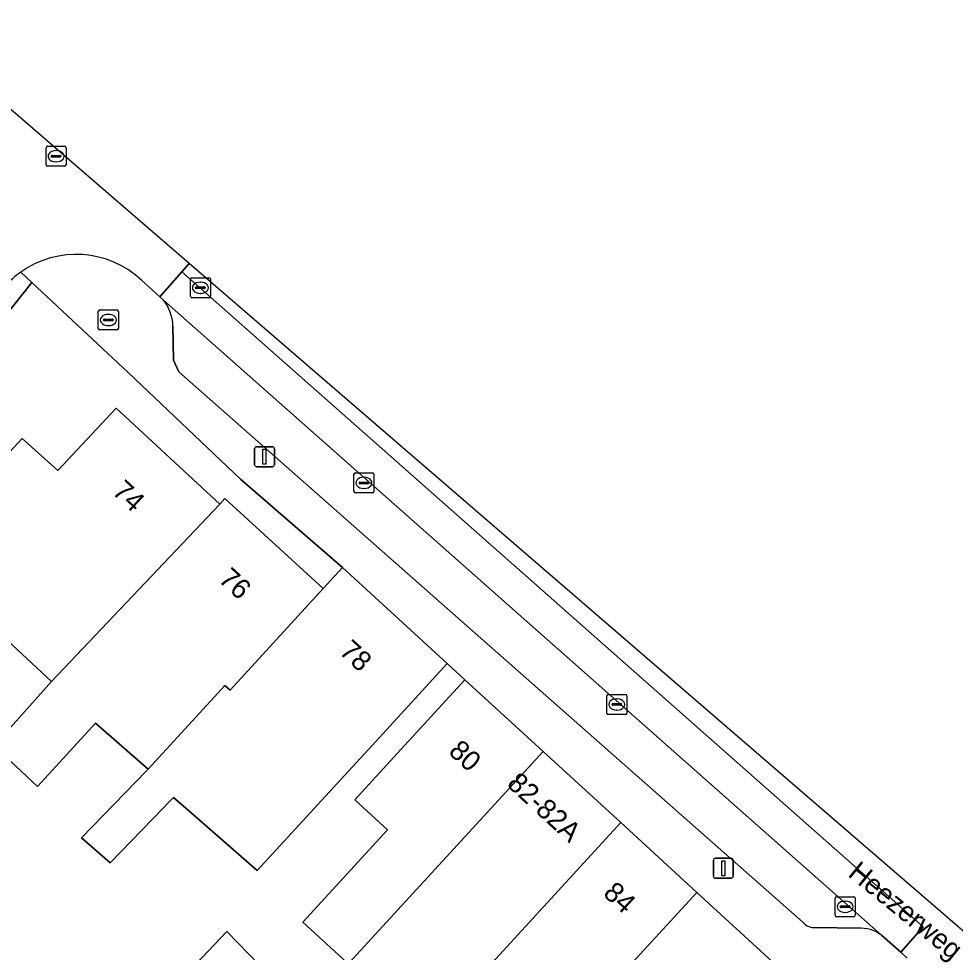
# Model space of a CAD drawing. Extents: x 161881 to 162523, y 381678 to 382381.
# Drawn here: x 162115.53 to 162162.08, y 382136.5 to 382183.09 of the extents above; entities that cross this region are included whole.
import ezdxf

# ---------------------------------------------------------------- set-up
doc = ezdxf.new("R2010")
doc.units = 0
for name, color, linetype in [('IMGEO_Brandkraan', 7, 'Continuous'), ('IMGEO_Erf', 7, 'Continuous'), ('IMGEO_Kolk', 7, 'Continuous'), ('IMGEO_Lichtmast', 7, 'Continuous'), ('IMGEO_Openbare_ruimte_label', 7, 'Continuous'), ('IMGEO_Pand', 7, 'Continuous'), ('IMGEO_Pand_nummerreeks', 7, 'Continuous'), ('IMGEO_Parkeervlak_open', 7, 'Continuous'), ('IMGEO_Rijbaan_lokaal_gesloten', 7, 'Continuous'), ('IMGEO_Rijbaan_lokaal_open', 7, 'Continuous'), ('IMGEO_Rioolput', 7, 'Continuous'), ('IMGEO_Voetpad_open', 7, 'Continuous')]:
    doc.layers.add(name, color=color, linetype=linetype)

msp = doc.modelspace()

# ---------------------------------------------------------------- linework, layer by layer
at = {"layer": 'IMGEO_Brandkraan'}
for p, q in [((162119.584, 382168.556), (162120.436, 382168.556)), ((162119.509, 382167.63), (162119.509, 382168.482)), ((162119.768, 382168.05), (162119.768, 382168.062)), ((162119.811, 382168.099), (162120.209, 382168.099)), ((162119.997, 382168.336), (162120.022, 382168.336)), ((162120.252, 382168.062), (162120.252, 382168.05)), ((162120.51, 382168.482), (162120.51, 382167.63)), ((162120.206, 382168.013), (162119.808, 382168.013)), ((162120.02, 382167.776), (162119.995, 382167.776)), ((162120.436, 382167.556), (162119.584, 382167.556))]:
    msp.add_line(p, q, dxfattribs=at)
for points in [[(162119.584, 382168.556), (162120.436, 382168.556)], [(162119.509, 382167.63), (162119.509, 382168.482)], [(162120.51, 382168.482), (162120.51, 382167.63)], [(162120.436, 382167.556), (162119.584, 382167.556)]]:
    msp.add_lwpolyline(points, dxfattribs=at)
for centre, radius, start, end in [((162119.586, 382168.48), 0.0765, 91.552, 178.448), ((162119.586, 382168.48), 0.0765, 91.552, 178.448), ((162120.434, 382168.48), 0.0765, 1.552, 88.448), ((162120.434, 382168.48), 0.0765, 1.552, 88.448), ((162119.808, 382168.059), 0.0403, 85.8775, 175.7526), ((162119.805, 382168.049), 0.0366, 178.938, 274.7102), ((162120.209, 382168.056), 0.043, 264.8664, 352.4533), ((162120.213, 382168.061), 0.0386, 1.7309, 96.639), ((162119.586, 382167.632), 0.0765, 181.552, 268.448), ((162119.586, 382167.632), 0.0765, 181.552, 268.448), ((162120.434, 382167.632), 0.0765, 271.552, 358.448), ((162120.434, 382167.632), 0.0765, 271.552, 358.448)]:
    msp.add_arc(centre, radius, start, end, dxfattribs=at)
for centre, major_axis, ratio, start_param, end_param in [((162119.996, 382168.056), (-0.387, 0.002), 0.722429, 4.712389, 7.853982), ((162120.021, 382168.056), (-0.39, 0.002), 0.717154, 1.570796, 4.712389)]:
    msp.add_ellipse(centre, major_axis=major_axis, ratio=ratio, start_param=start_param, end_param=end_param, dxfattribs=at)
at = {"layer": 'IMGEO_Erf'}
for points in [[(162112.301, 382158.48), (162115.707, 382162.139), (162117.492, 382160.54), (162120.395, 382163.662), (162125.568, 382158.867), (162125.829, 382159.152), (162130.734, 382154.653), (162131.693, 382155.698), (162126.612, 382160.118), (162121.003, 382165.434), (162116.187, 382169.927), (162097.305, 382146.167)], [(162131.894, 382136.009), (162129.716, 382138.006), (162133.943, 382142.615), (162132.309, 382144.112), (162134.424, 382146.419), (162137.803, 382150.104), (162136.914, 382150.91), (162133.535, 382147.226), (162131.051, 382144.517), (162127.442, 382140.582), (162124.386, 382143.249), (162124.15, 382143.466), (162123.259, 382144.232), (162123.015, 382143.98), (162122.764, 382143.72), (162120.096, 382140.962), (162118.667, 382142.21), (162121.906, 382145.559), (162121.989, 382145.649), (162119.367, 382147.936), (162116.48, 382144.785), (162114.301, 382146.812), (162117.176, 382150.009), (162110.339, 382156.373)], [(162120.058, 382131.359), (162125.918, 382137.539), (162129.757, 382133.588)]]:
    msp.add_lwpolyline(points, dxfattribs=at)
at = {"layer": 'IMGEO_Kolk'}
for p, q in [((162132.263, 382159.501), (162132.263, 382160.353)), ((162132.338, 382160.427), (162133.19, 382160.427)), ((162132.751, 382160.207), (162132.776, 382160.207)), ((162133.264, 382160.353), (162133.264, 382159.501)), ((162132.522, 382159.921), (162132.522, 382159.933)), ((162132.96, 382159.884), (162132.562, 382159.884)), ((162132.565, 382159.97), (162132.963, 382159.97)), ((162132.774, 382159.647), (162132.749, 382159.647)), ((162133.006, 382159.933), (162133.006, 382159.921)), ((162133.19, 382159.427), (162132.338, 382159.427)), ((162144.88, 382148.444), (162144.88, 382149.296)), ((162144.955, 382149.37), (162145.807, 382149.37)), ((162145.368, 382149.15), (162145.393, 382149.15)), ((162145.881, 382149.296), (162145.881, 382148.444)), ((162145.139, 382148.864), (162145.139, 382148.876)), ((162145.577, 382148.827), (162145.179, 382148.827)), ((162145.182, 382148.913), (162145.58, 382148.913)), ((162145.391, 382148.59), (162145.366, 382148.59)), ((162145.623, 382148.876), (162145.623, 382148.864)), ((162145.807, 382148.37), (162144.955, 382148.37)), ((162156.274, 382138.351), (162156.274, 382139.203)), ((162156.349, 382139.277), (162157.201, 382139.277)), ((162157.275, 382139.203), (162157.275, 382138.351)), ((162156.533, 382138.771), (162156.533, 382138.783)), ((162156.971, 382138.734), (162156.573, 382138.734)), ((162156.576, 382138.82), (162156.974, 382138.82)), ((162156.762, 382139.057), (162156.787, 382139.057)), ((162157.017, 382138.783), (162157.017, 382138.771)), ((162157.201, 382138.277), (162156.349, 382138.277)), ((162156.785, 382138.497), (162156.76, 382138.497))]:
    msp.add_line(p, q, dxfattribs=at)
for points in [[(162132.263, 382159.501), (162132.263, 382160.353)], [(162132.338, 382160.427), (162133.19, 382160.427)], [(162133.264, 382160.353), (162133.264, 382159.501)], [(162133.19, 382159.427), (162132.338, 382159.427)], [(162144.88, 382148.444), (162144.88, 382149.296)], [(162144.955, 382149.37), (162145.807, 382149.37)], [(162145.881, 382149.296), (162145.881, 382148.444)], [(162145.807, 382148.37), (162144.955, 382148.37)], [(162156.274, 382138.351), (162156.274, 382139.203)], [(162156.349, 382139.277), (162157.201, 382139.277)], [(162157.275, 382139.203), (162157.275, 382138.351)], [(162157.201, 382138.277), (162156.349, 382138.277)]]:
    msp.add_lwpolyline(points, dxfattribs=at)
for centre, radius, start, end in [((162132.34, 382160.351), 0.0765, 91.552, 178.448), ((162132.34, 382160.351), 0.0765, 91.552, 178.448), ((162133.188, 382160.351), 0.0765, 1.552, 88.448), ((162133.188, 382160.351), 0.0765, 1.552, 88.448), ((162132.562, 382159.93), 0.0403, 85.8775, 175.7526), ((162132.559, 382159.92), 0.0366, 178.938, 274.7102), ((162132.963, 382159.927), 0.043, 264.8664, 352.4533), ((162132.967, 382159.932), 0.0386, 1.7309, 96.639), ((162132.34, 382159.503), 0.0765, 181.552, 268.448), ((162132.34, 382159.503), 0.0765, 181.552, 268.448), ((162133.188, 382159.503), 0.0765, 271.552, 358.448), ((162133.188, 382159.503), 0.0765, 271.552, 358.448), ((162144.957, 382149.294), 0.0765, 91.552, 178.448), ((162144.957, 382149.294), 0.0765, 91.552, 178.448), ((162145.805, 382149.294), 0.0765, 1.552, 88.448), ((162145.805, 382149.294), 0.0765, 1.552, 88.448), ((162145.179, 382148.873), 0.0403, 85.8775, 175.7526), ((162145.176, 382148.863), 0.0366, 178.938, 274.7102), ((162145.58, 382148.87), 0.043, 264.8664, 352.4533), ((162145.584, 382148.875), 0.0386, 1.7309, 96.639), ((162144.957, 382148.446), 0.0765, 181.552, 268.448), ((162144.957, 382148.446), 0.0765, 181.552, 268.448), ((162145.805, 382148.446), 0.0765, 271.552, 358.448), ((162145.805, 382148.446), 0.0765, 271.552, 358.448), ((162156.351, 382139.201), 0.0765, 91.552, 178.448), ((162156.351, 382139.201), 0.0765, 91.552, 178.448), ((162157.199, 382139.201), 0.0765, 1.552, 88.448), ((162157.199, 382139.201), 0.0765, 1.552, 88.448), ((162156.573, 382138.78), 0.0403, 85.8775, 175.7526), ((162156.57, 382138.77), 0.0366, 178.938, 274.7102), ((162156.974, 382138.777), 0.043, 264.8664, 352.4533), ((162156.978, 382138.782), 0.0386, 1.7309, 96.639), ((162156.351, 382138.353), 0.0765, 181.552, 268.448), ((162156.351, 382138.353), 0.0765, 181.552, 268.448), ((162157.199, 382138.353), 0.0765, 271.552, 358.448), ((162157.199, 382138.353), 0.0765, 271.552, 358.448)]:
    msp.add_arc(centre, radius, start, end, dxfattribs=at)
for centre, major_axis, ratio, start_param, end_param in [((162132.75, 382159.927), (-0.387, 0.002), 0.722429, 4.712389, 7.853982), ((162132.775, 382159.927), (-0.39, 0.002), 0.717154, 1.570796, 4.712389), ((162145.367, 382148.87), (-0.387, 0.002), 0.722429, 4.712389, 7.853982), ((162145.392, 382148.87), (-0.39, 0.002), 0.717154, 1.570796, 4.712389), ((162156.761, 382138.777), (-0.387, 0.002), 0.722429, 4.712389, 7.853982), ((162156.786, 382138.777), (-0.39, 0.002), 0.717154, 1.570796, 4.712389)]:
    msp.add_ellipse(centre, major_axis=major_axis, ratio=ratio, start_param=start_param, end_param=end_param, dxfattribs=at)
at = {"layer": 'IMGEO_Lichtmast'}
for p, q in [((162127.306, 382160.831), (162127.306, 382161.631)), ((162127.306, 382161.631), (162127.306, 382160.831)), ((162127.406, 382161.731), (162128.196, 382161.731)), ((162128.196, 382161.731), (162127.406, 382161.731)), ((162128.296, 382161.631), (162128.296, 382160.831)), ((162128.296, 382160.831), (162128.296, 382161.631)), ((162128.196, 382160.731), (162127.406, 382160.731)), ((162127.406, 382160.731), (162128.196, 382160.731)), ((162150.201, 382140.3), (162150.201, 382141.1)), ((162150.201, 382141.1), (162150.201, 382140.3)), ((162150.301, 382141.2), (162151.091, 382141.2)), ((162151.091, 382141.2), (162150.301, 382141.2)), ((162151.191, 382141.1), (162151.191, 382140.3)), ((162151.191, 382140.3), (162151.191, 382141.1)), ((162151.091, 382140.2), (162150.301, 382140.2)), ((162150.301, 382140.2), (162151.091, 382140.2))]:
    msp.add_line(p, q, dxfattribs=at)
for points in [[(162127.726, 382161.606), (162127.876, 382161.606), (162127.876, 382160.856), (162127.726, 382160.856), (162127.726, 382161.606)], [(162150.621, 382141.075), (162150.771, 382141.075), (162150.771, 382140.325), (162150.621, 382140.325), (162150.621, 382141.075)]]:
    msp.add_lwpolyline(points, dxfattribs=at)
for centre, start, end in [((162127.406, 382161.631), 90, 180), ((162127.406, 382161.631), 90, 180), ((162128.196, 382161.631), 0, 90), ((162128.196, 382161.631), 360, 90), ((162127.406, 382160.831), 180, 270), ((162127.406, 382160.831), 180, 270), ((162128.196, 382160.831), 270, 0), ((162128.196, 382160.831), 270, 0), ((162150.301, 382141.1), 90, 180), ((162150.301, 382141.1), 90, 180), ((162151.091, 382141.1), 0, 90), ((162151.091, 382141.1), 360, 90), ((162150.301, 382140.3), 180, 270), ((162150.301, 382140.3), 180, 270), ((162151.091, 382140.3), 270, 0), ((162151.091, 382140.3), 270, 0)]:
    msp.add_arc(centre, 0.1, start, end, dxfattribs=at)
at = {"layer": 'IMGEO_Pand'}
for points in [[(162125.568, 382158.867), (162120.395, 382163.662), (162117.492, 382160.54), (162115.707, 382162.139), (162112.301, 382158.48), (162110.339, 382156.373), (162117.176, 382150.009)], [(162130.734, 382154.653), (162125.829, 382159.152), (162125.568, 382158.867), (162117.176, 382150.009), (162114.301, 382146.812), (162116.48, 382144.785), (162119.367, 382147.936), (162121.989, 382145.649), (162125.818, 382149.824), (162126.084, 382149.58)], [(162133.535, 382147.226), (162136.914, 382150.91), (162131.693, 382155.698), (162130.734, 382154.653), (162126.084, 382149.58), (162125.818, 382149.824), (162121.989, 382145.649), (162121.906, 382145.559), (162118.667, 382142.21), (162120.096, 382140.962), (162122.764, 382143.72), (162123.015, 382143.98), (162123.259, 382144.232), (162124.15, 382143.466), (162124.386, 382143.249), (162127.442, 382140.582), (162131.051, 382144.517)], [(162141.709, 382146.522), (162137.803, 382150.104), (162134.424, 382146.419), (162132.309, 382144.112), (162133.943, 382142.615), (162129.716, 382138.006), (162131.894, 382136.009), (162131.669, 382135.938), (162131.849, 382135.773)], [(162145.576, 382142.975), (162141.709, 382146.522), (162131.849, 382135.773), (162133.827, 382133.959), (162135.557, 382132.207), (162134.295, 382130.91), (162134.405, 382130.798)], [(162145.576, 382142.975), (162134.405, 382130.798), (162136.056, 382129.125), (162137.342, 382130.446), (162139.366, 382128.589), (162149.37, 382139.496)], [(162153.156, 382136.024), (162149.37, 382139.496), (162139.366, 382128.589), (162141.02, 382127.073), (162146.041, 382131.663), (162147.597, 382130.236), (162147.733, 382130.112)], [(162129.757, 382133.588), (162125.918, 382137.539), (162120.058, 382131.359), (162123.474, 382126.921), (162125.219, 382128.746)]]:
    msp.add_lwpolyline(points, close=True, dxfattribs=at)
at = {"layer": 'IMGEO_Parkeervlak_open'}
for points in [[(162158.594, 382137.366), (162122.761, 382169.05)], [(162123.234, 382167.756), (162123.255, 382166.055), (162123.53, 382165.475), (162154.673, 382138.002)], [(162155.314, 382137.743), (162157.422, 382137.712)]]:
    msp.add_lwpolyline(points, dxfattribs=at)
for centre, radius, start, end in [((162120.959, 382167.658), 2.277, 2.4707, 37.6873), ((162155.245, 382138.496), 0.756, 220.7893, 275.2078), ((162157.488, 382135.779), 1.934, 55.1377, 91.9668)]:
    msp.add_arc(centre, radius, start, end, dxfattribs=at)
at = {"layer": 'IMGEO_Rijbaan_lokaal_gesloten'}
msp.add_lwpolyline([(162123.677, 382170.45), (162122.586, 382169.208), (162122.761, 382169.05), (162158.594, 382137.366), (162159.551, 382136.515), (162160.677, 382137.773)], close=True, dxfattribs=at)
at = {"layer": 'IMGEO_Rijbaan_lokaal_open'}
for points in [[(162124.046, 382170.871), (162109.883, 382183.088), (162109.659, 382182.83), (162108.526, 382181.527), (162109.411, 382180.74)], [(162121.671, 382170.036), (162122.586, 382169.208), (162123.677, 382170.45), (162124.046, 382170.871)], [(162196.622, 382109.326), (162181.661, 382121.174), (162166.369, 382134.365), (162124.046, 382170.871), (162123.677, 382170.45), (162160.677, 382137.773), (162159.551, 382136.515), (162159.877, 382136.204)]]:
    msp.add_lwpolyline(points, dxfattribs=at)
for centre, radius, start, end in [((162118.407, 382166.555), 4.772, 46.8426, 125.4359), ((162118.467, 382166.491), 4.859, 125.5799, 138.0391)]:
    msp.add_arc(centre, radius, start, end, dxfattribs=at)
at = {"layer": 'IMGEO_Rioolput'}
for p, q in [((162116.899, 382175.798), (162116.899, 382176.65)), ((162116.974, 382176.724), (162117.826, 382176.724)), ((162117.387, 382176.504), (162117.412, 382176.504)), ((162117.9, 382176.65), (162117.9, 382175.798)), ((162117.158, 382176.218), (162117.158, 382176.23)), ((162117.596, 382176.181), (162117.198, 382176.181)), ((162117.201, 382176.267), (162117.599, 382176.267)), ((162117.41, 382175.944), (162117.385, 382175.944)), ((162117.642, 382176.23), (162117.642, 382176.218)), ((162117.826, 382175.724), (162116.974, 382175.724)), ((162124.103, 382169.235), (162124.103, 382170.087)), ((162124.178, 382170.161), (162125.03, 382170.161)), ((162124.591, 382169.941), (162124.616, 382169.941)), ((162125.104, 382170.087), (162125.104, 382169.235)), ((162124.362, 382169.655), (162124.362, 382169.667)), ((162124.8, 382169.618), (162124.402, 382169.618)), ((162124.405, 382169.704), (162124.803, 382169.704)), ((162124.846, 382169.667), (162124.846, 382169.655)), ((162125.03, 382169.161), (162124.178, 382169.161)), ((162124.614, 382169.381), (162124.589, 382169.381))]:
    msp.add_line(p, q, dxfattribs=at)
for points in [[(162116.899, 382175.798), (162116.899, 382176.65)], [(162116.974, 382176.724), (162117.826, 382176.724)], [(162117.9, 382176.65), (162117.9, 382175.798)], [(162117.826, 382175.724), (162116.974, 382175.724)], [(162124.103, 382169.235), (162124.103, 382170.087)], [(162124.178, 382170.161), (162125.03, 382170.161)], [(162125.104, 382170.087), (162125.104, 382169.235)], [(162125.03, 382169.161), (162124.178, 382169.161)]]:
    msp.add_lwpolyline(points, dxfattribs=at)
for centre, radius, start, end in [((162116.976, 382176.648), 0.0765, 91.552, 178.448), ((162116.976, 382176.648), 0.0765, 91.552, 178.448), ((162117.824, 382176.648), 0.0765, 1.552, 88.448), ((162117.824, 382176.648), 0.0765, 1.552, 88.448), ((162117.198, 382176.227), 0.0403, 85.8775, 175.7526), ((162117.195, 382176.217), 0.0366, 178.938, 274.7102), ((162117.599, 382176.224), 0.043, 264.8664, 352.4533), ((162117.603, 382176.229), 0.0386, 1.7309, 96.639), ((162116.976, 382175.8), 0.0765, 181.552, 268.448), ((162116.976, 382175.8), 0.0765, 181.552, 268.448), ((162117.824, 382175.8), 0.0765, 271.552, 358.448), ((162117.824, 382175.8), 0.0765, 271.552, 358.448), ((162124.18, 382170.085), 0.0765, 91.552, 178.448), ((162124.18, 382170.085), 0.0765, 91.552, 178.448), ((162125.028, 382170.085), 0.0765, 1.552, 88.448), ((162125.028, 382170.085), 0.0765, 1.552, 88.448), ((162124.402, 382169.664), 0.0403, 85.8775, 175.7526), ((162124.399, 382169.654), 0.0366, 178.938, 274.7102), ((162124.803, 382169.661), 0.043, 264.8664, 352.4533), ((162124.807, 382169.666), 0.0386, 1.7309, 96.639), ((162124.18, 382169.237), 0.0765, 181.552, 268.448), ((162124.18, 382169.237), 0.0765, 181.552, 268.448), ((162125.028, 382169.237), 0.0765, 271.552, 358.448), ((162125.028, 382169.237), 0.0765, 271.552, 358.448)]:
    msp.add_arc(centre, radius, start, end, dxfattribs=at)
for centre, major_axis, ratio, start_param, end_param in [((162117.386, 382176.224), (-0.387, 0.002), 0.722429, 4.712389, 7.853982), ((162117.411, 382176.224), (-0.39, 0.002), 0.717154, 1.570796, 4.712389), ((162124.59, 382169.661), (-0.387, 0.002), 0.722429, 4.712389, 7.853982), ((162124.615, 382169.661), (-0.39, 0.002), 0.717154, 1.570796, 4.712389)]:
    msp.add_ellipse(centre, major_axis=major_axis, ratio=ratio, start_param=start_param, end_param=end_param, dxfattribs=at)
at = {"layer": 'IMGEO_Voetpad_open'}
for points in [[(162116.187, 382169.927), (162115.64, 382170.443)], [(162115.64, 382170.443), (162116.187, 382169.927), (162121.003, 382165.434), (162126.612, 382160.118), (162131.693, 382155.698), (162136.914, 382150.91), (162137.803, 382150.104), (162141.709, 382146.522), (162145.576, 382142.975), (162149.37, 382139.496), (162153.156, 382136.024), (162157.689, 382131.867), (162158.024, 382129.831), (162157.745, 382129.743), (162155.369, 382126.625), (162157.239, 382125.145), (162160.442, 382129.245)], [(162114.854, 382169.74), (162114.197, 382168.912), (162112.854, 382167.219), (162105.104, 382157.423), (162097.375, 382147.693), (162096.592, 382146.719), (162097.305, 382146.167), (162116.187, 382169.927)], [(162122.761, 382169.05), (162122.586, 382169.208), (162121.671, 382170.036)], [(162123.53, 382165.475), (162123.255, 382166.055), (162123.234, 382167.756)], [(162154.673, 382138.002), (162123.53, 382165.475)], [(162157.422, 382137.712), (162155.314, 382137.743)], [(162159.877, 382136.204), (162159.551, 382136.515), (162158.594, 382137.366)]]:
    msp.add_lwpolyline(points, dxfattribs=at)
for centre, radius, start, end in [((162118.407, 382166.555), 4.772, 46.8426, 125.4359), ((162118.467, 382166.491), 4.859, 125.5799, 138.0391), ((162120.959, 382167.658), 2.277, 2.4707, 37.6873), ((162155.245, 382138.496), 0.756, 220.7893, 275.2078), ((162157.488, 382135.779), 1.934, 55.1377, 91.9668)]:
    msp.add_arc(centre, radius, start, end, dxfattribs=at)

# ---------------------------------------------------------------- texts
at = {"layer": 'IMGEO_Openbare_ruimte_label'}
msp.add_text('Heezerweg', height=1, rotation=320.8839, dxfattribs=at).set_placement((162156.867, 382140.342))
at = {"layer": 'IMGEO_Pand_nummerreeks'}
for s, rotation, p in [('74', 317.1714, (162120.146, 382159.421)), ('76', 317.4693, (162125.456, 382155.044)), ('78', 317.4751, (162131.48, 382151.444)), ('80', 317.4768, (162136.933, 382146.453)), ('82-82A', 317.4693, (162139.845, 382144.839)), ('84', 317.4768, (162144.648, 382139.377))]:
    msp.add_text(s, height=1, rotation=rotation, dxfattribs=at).set_placement(p)

doc.saveas('drawing.dxf')
